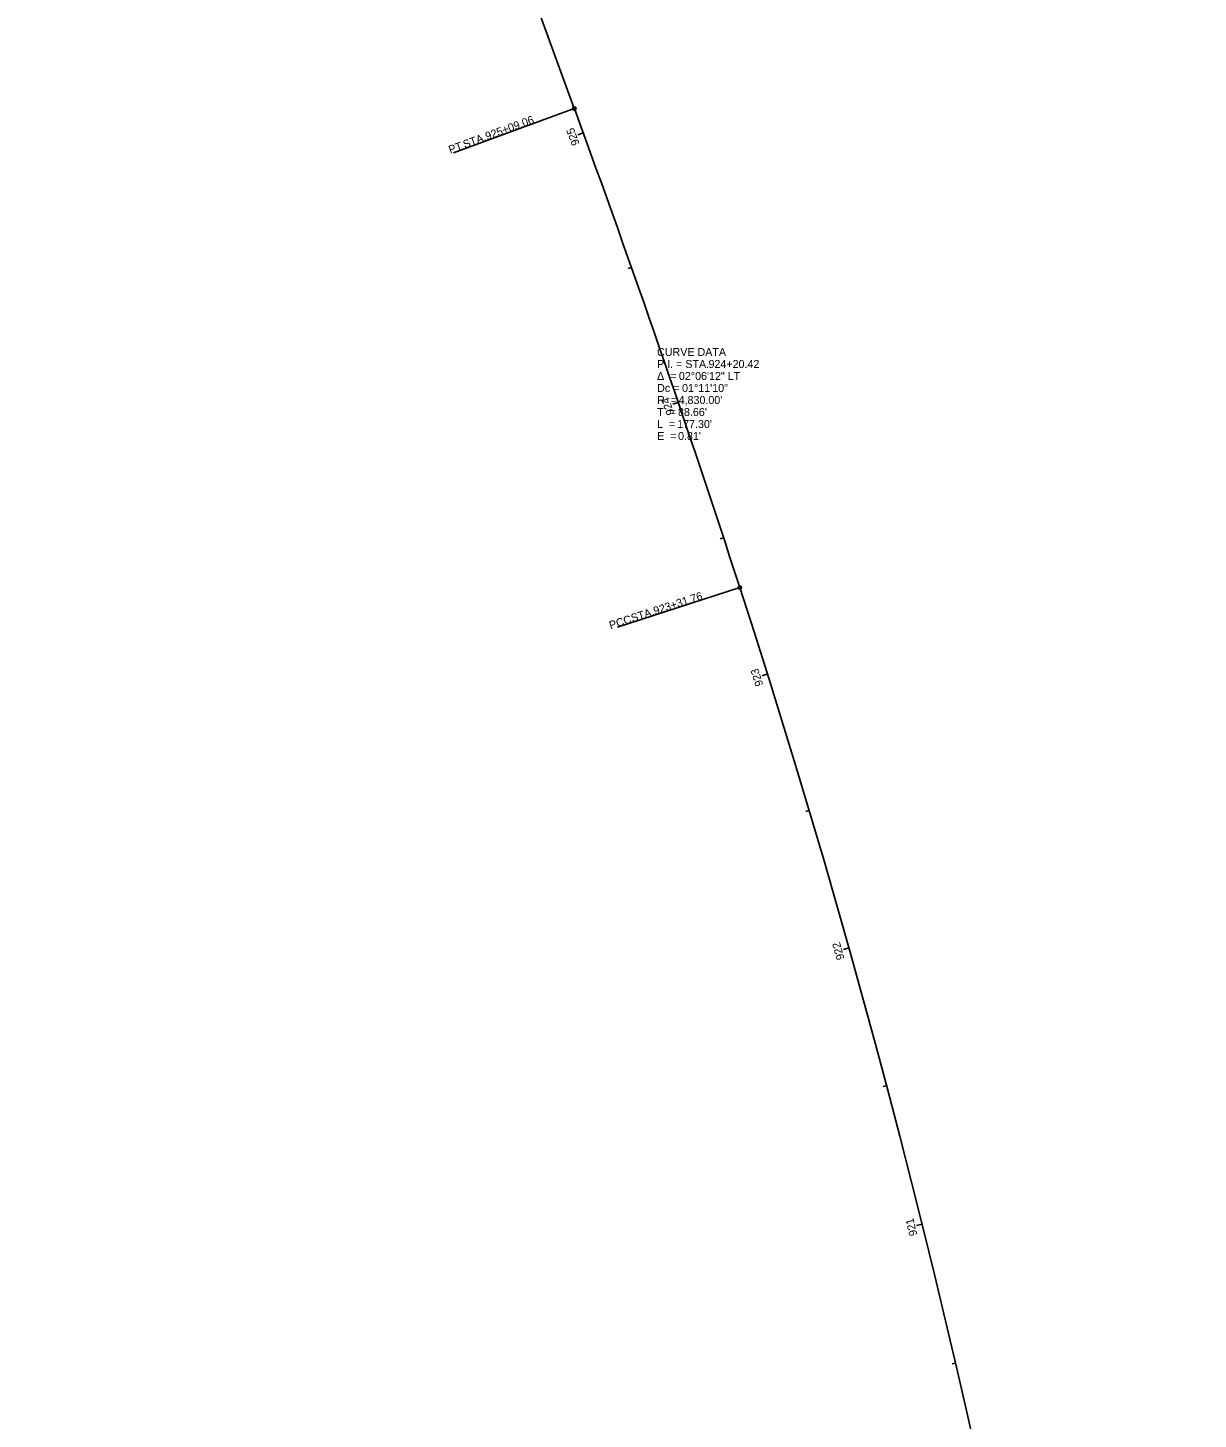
# Model space of a CAD drawing. Extents: x 145633 to 146120, y 414528 to 417535.
# Drawn here: x 145678.1 to 146087.6, y 416553.3 to 417040 of the extents above; entities that cross this region are included whole.
import ezdxf

# ---------------------------------------------------------------- set-up
doc = ezdxf.new("R2010")
doc.units = 0
for name, color, linetype in [('GE_X_Alignment', 7, 'Continuous'), ('GE_X_Alignment_100_Cardinal_Points', 7, 'Continuous'), ('GE_X_Alignment_100_Curve_Data', 7, 'Continuous'), ('GE_X_Alignment_100_Stations', 7, 'Continuous'), ('SC_Scratch3', 7, 'Continuous')]:
    doc.layers.add(name, color=color, linetype=linetype)

msp = doc.modelspace()

# ---------------------------------------------------------------- linework, layer by layer
at = {"layer": 'GE_X_Alignment'}
msp.add_line((145869.32, 417011.82), (145678.13, 417534.01), dxfattribs=at)
for centre, radius, start, end in [((141333.78, 415351.18), 4830, 18.00643, 20.10968), ((142813.52, 415832.16), 3274.05, 359.36198, 18.00643)]:
    msp.add_arc(centre, radius, start, end, dxfattribs=at)
at = {"layer": 'GE_X_Alignment_100_Cardinal_Points'}
for p, q in [((145869.32, 417011.82), (145827.07, 416996.35)), ((145927.21, 416844.24), (145884.42, 416830.33))]:
    msp.add_line(p, q, dxfattribs=at)
for centre in [(145869.32, 417011.82), (145927.21, 416844.24)]:
    msp.add_circle(centre, 0.6, dxfattribs=at)
at = {"layer": 'GE_X_Alignment_100_Stations'}
for p, q in [((145872.43, 417003.31), (145870.55, 417002.62)), ((145889.29, 416956.24), (145888.16, 416955.84)), ((145905.66, 416908.99), (145903.77, 416908.35)), ((145921.54, 416861.58), (145920.4, 416861.21)), ((145936.89, 416813.99), (145934.98, 416813.39)), ((145951.51, 416766.18), (145950.36, 416765.84)), ((145965.41, 416718.15), (145963.49, 416717.61)), ((145978.57, 416669.92), (145977.41, 416669.61)), ((145991, 416621.49), (145989.06, 416621)), ((146002.68, 416572.87), (146001.51, 416572.6))]:
    msp.add_line(p, q, dxfattribs=at)
at = {"layer": 'SC_Scratch3'}
msp.add_line((145678.13, 417534.01), (145869.32, 417011.82), dxfattribs=at)
for centre, radius, start, end in [((141333.78, 415351.18), 4830, 18.00643, 20.10968), ((142813.52, 415832.16), 3274.05, 359.36198, 18.00643)]:
    msp.add_arc(centre, radius, start, end, dxfattribs=at)

# ---------------------------------------------------------------- texts
at = {"layer": 'GE_X_Alignment_100_Cardinal_Points'}
for s, rotation, p in [('925+09.06', 20.1097, (145838.77, 417000.67)), (' STA. ', 20.1097, (145830.01, 416997.46)), ('PT', 20.1097, (145825.93, 416995.97)), ('923+31.76', 18.0064, (145897.51, 416834.63)), (' STA. ', 18.0064, (145888.65, 416831.75)), ('PCC', 18.0064, (145882.03, 416829.59))]:
    msp.add_text(s, height=2.8, rotation=rotation, dxfattribs=at).set_placement(p)
at = {"layer": 'GE_X_Alignment_100_Curve_Data'}
for s, p in [('CURVE DATA', (145898.27, 416925.23)), ('P.I. = STA. ', (145898.27, 416921.03)), ('924+20.42', (145916.26, 416921.03)), ('Δ  = ', (145898.27, 416916.83)), ('02°06\'12" LT', (145905.91, 416916.83)), ('Dc = ', (145898.27, 416912.63)), ('01°11\'10"', (145907.01, 416912.63)), ('R  = ', (145898.27, 416908.43)), ("4,830.00'", (145905.8, 416908.43)), ('T  = ', (145898.27, 416904.23)), ("88.66'", (145905.59, 416904.23)), ('L  = ', (145898.27, 416900.03)), ('E  = ', (145898.27, 416895.83)), ("177.30'", (145905.3, 416900.03)), ("0.81'", (145905.61, 416895.83))]:
    msp.add_text(s, height=2.8, dxfattribs=at).set_placement(p)
at = {"layer": 'GE_X_Alignment_100_Stations'}
for s, rotation, p in [('925', 110.0022, (145871.18, 416999.44)), ('924', 108.8159, (145904.35, 416905.08)), ('923', 107.4507, (145935.46, 416810.19)), ('922', 105.7007, (145963.87, 416714.38)), ('921', 103.9507, (145989.35, 416617.75))]:
    msp.add_text(s, height=2.8, rotation=rotation, dxfattribs=at).set_placement(p)

doc.saveas('drawing.dxf')
